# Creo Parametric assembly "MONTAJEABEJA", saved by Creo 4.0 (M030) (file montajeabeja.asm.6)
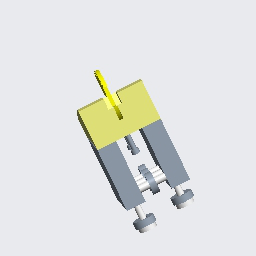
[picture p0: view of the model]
Units: millimeter Newton Second (mmNs); MM, TONNE, SECS

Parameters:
  MODELED_BY = "aj"

Created from: MMNS_ASM_DESIGN.ASM

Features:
  1. datum plane "ASM_RIGHT"
  2. datum plane "ASM_TOP"
  3. datum plane "ASM_FRONT"
  4. coordinate system
  5. component "LADOSUNIONESABEJA"
  6. component "EJECENTROABEJA"
  7. component "EJECENTROABEJA"
  8. component "EJECENTROABEJA"
  9. component "LADOSUNIONESABEJA"
  10. component "EJELATERALABEJA"
  11. component "EJELATERALABEJA"
  12. component "EJERUEDASCENTROABEJA"
  13. component "RODAMIENTOABEJA"
  14. component "SOPORTEPESO"
  15. component "EJERUEDASCENTROABEJA"
  16. component "RODAMIENTOABEJA"
  17. component "SOPORTEPESO"
  18. component "ELEVADORABEJA"
  19. component "ABEJAENSI"

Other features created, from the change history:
  component "LADOSUNIONESABEJA.PRT"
